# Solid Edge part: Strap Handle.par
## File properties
Document Number: DOC NUMBER
Revision: REV NUMBER
Project Name: COFFEE MAKER
Title: STRAP HANDLE
Subject: COFFEE MAKER
Author: rkriggs
Keywords: STRAP
Comments: COMMENTS FIELD
Template: Normal.par
Last saved by: plm
Revision: 33
Application: Solid Edge
Category: COFFEE MAKER
Manager: MANAGER FIELD
Company: UGS
CUSTOM NAME FIELD: CUSTOM VALUE FIELD
Density: 0.279986513 lbm/in^3
Accuracy: 0.99
圖檔名稱: Strap Handle
圖檔編號: Strap Handle
major_rev: A
classification: Mechanical/Part
generation: 2
id: A4C8E423BF1941A7A3B0710E2A28CFC0
thumbnail: vault:///?fileId=3A97535F4C9C431BB7E6B3B61A2C3692
authoring_tool: Solid Edge
Material: Stainless steel
Face Style: Silver
Fill Style: ANSI32(Steel)
Virtual Style: Stainless steel
Coef. of Thermal Exp: 1.6e-05
Thermal Conductivity: 17.0
Specific Heat: 502.0
Modulus of Elasticity: 193053196000.0
Poisson's Ratio: 0.29
Yield Stress: 310264065.0
Ultimate Stress: 641212401.0
Elongation: 0.0
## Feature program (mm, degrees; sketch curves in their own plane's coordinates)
pattern "unnamed Pattern 1"
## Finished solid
Body 1: solid body, 25 faces, 74 edges, 48 vertices.
  Faces by surface: plane 14, cylinder 11
  Edges by curve: line 44, circle 30
Bounding box of the edges (mm): 127.674 x 114.300 x 11.100, from (-70.5237, -57.15, -11.0998) to (57.15, 57.15, 0).
Cylindrical faces by radius (mm): R0.381 x4, R0.762 x4, R1.5875 x1, R56.388 x1, R57.15 x1
Planar faces by outward normal: +x 1, +y 4, +z 2, -x 1, -y 4, -z 2
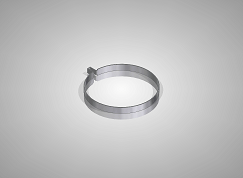
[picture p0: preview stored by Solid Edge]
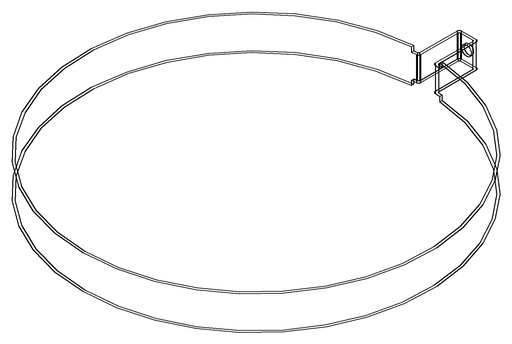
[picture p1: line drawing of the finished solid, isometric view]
